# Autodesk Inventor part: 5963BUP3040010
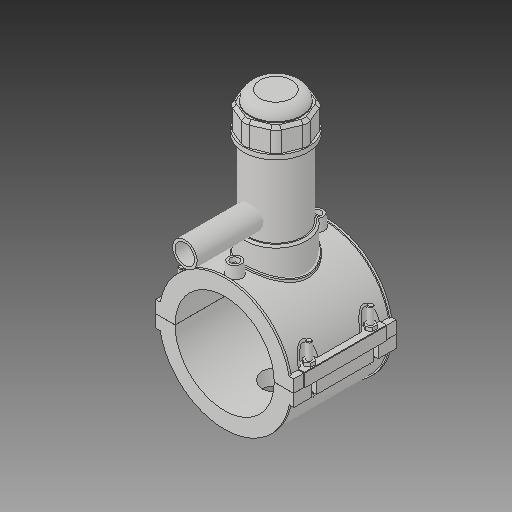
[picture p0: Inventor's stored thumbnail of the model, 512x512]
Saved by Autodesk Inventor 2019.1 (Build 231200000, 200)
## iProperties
Created: 2017-07
Part Number: 5963BUP3040010
Material: Generic
Description: PLASSON TAPPING SADDLE 4''IPS x 1''CTS
Document SubType Name: Modeling
Designer: KIM
Density: 1 g/cm^3
Appearance: Default
Author: KIM
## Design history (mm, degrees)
derived "5963BBP_5963BUP.ipt"
feature "Solid1::5963BBP_5963BUP.ipt"
feature "Solid2::5963BBP_5963BUP.ipt"
feature "Solid3::5963BBP_5963BUP.ipt"
tag "TaggingFeature1"
body "Solid1"
body "Solid2"
body "Solid3"
other parameters: "d0" = 114.1, "d2" = 159.004, "d3" = 28.525, "d4" = 118.11, "d5" = 0, "d6" = 0.1, "d8" = 0, "d19" = 6, "d20" = 6, "d21" = 70.866, "d23" = 0, "d24" = 35.433, "d26" = 0, "d27" = 3, "d28" = 3, "d29" = 3, "d30" = 38.03333, "d31" = 6, "d32" = 0, "d33" = 0, "d34" = 0.6, "d40" = 77.1316, "d41" = 74.165, "d43" = 0, "d45" = 0, "d47" = 145.031, "d70" = 15, "d72" = 0, "d73" = 6, "d75" = 5, "d76" = 0, "d77" = 5.705, "d78" = 87.05, "d79" = 15, "d80" = 47.244, "d82" = 5 deg, "d84" = 4, "d85" = 14, "d86" = 0, "d87" = 3, "d88" = 0, "d89" = 1, "d90" = 1, "d91" = 94.488, "d92" = 0, "d93" = 0.5, "d94" = 60.05263, "d96" = 151.2966, "d97" = 2.3622, "d98" = 0, "d102" = 1.141, "d120" = 140 deg, "d121" = 24.228, "d122" = 20 deg, "d123" = 296.66, "d124" = 88.998, "d126" = 0, "d143" = 117.523, "d145" = 26.33077, "d149" = 1.7115, "d150" = 28.96385, "d153" = 118.11, "d154" = 0, "d156" = 74.165, "d157" = 160 deg, "d159" = 6.846, "d161" = 1.7115, "d162" = 70.866, "d163" = 0, "d164" = 57.05, "d167" = 11.41, "d168" = 72.3561, "d170" = 3.2805, "d172" = 0, "d173" = 1, "d175" = 57.05, "d176" = 20 deg, "d177" = 7.987, "d178" = 34.23, "d180" = 0, "d183" = 13.692, "d184" = 6.3896, "d185" = 38.38575, "d186" = 38.38575, "d187" = 74.165, "d188" = 10.269, "d189" = 7.987, "d190" = 0, "d191" = 111.2475, "d193" = 6.9984, "d194" = 4.13385, "d195" = 90 deg, "d197" = 0, "d199" = 0, "d200" = 17.115, "d202" = 0, "d203" = 177.038, "d204" = 70.45675, "d205" = 51.9155, "d206" = 63.04025, "d207" = 132.7785, "d208" = 138.08964, "d209" = 164.64534, "d210" = 63.7819, "d211" = 74.165, "d212" = 59.332, "d213" = 45.7191, "d216" = 0, "d217" = 11.41, "d218" = 11.41, "d219" = 2.282, "d222" = 114.1, "d224" = 0, "d225" = 65.024, "d226" = 28.45, "d227" = 22.76, "d228" = 104.902, "d230" = 3.423, "d_" = 114.1, "B_" = 159.004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
